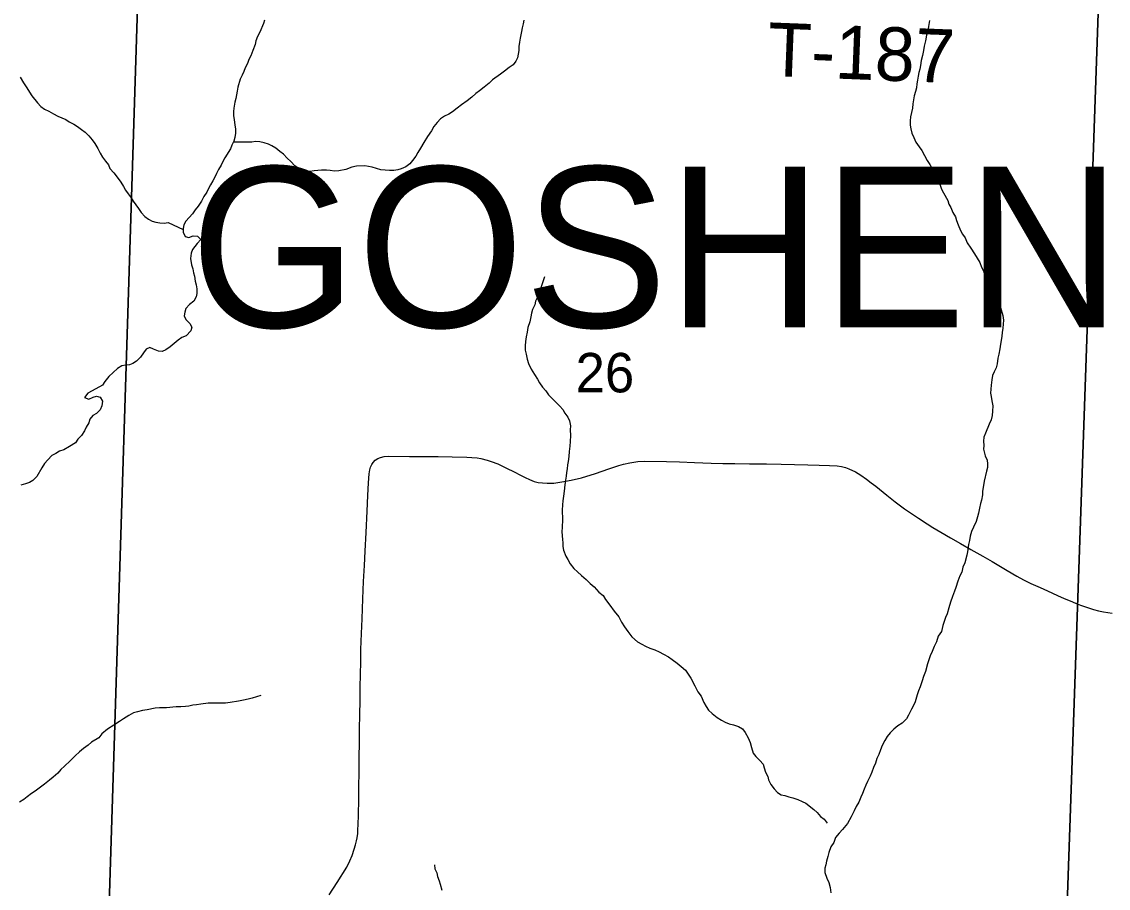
# Model space of a CAD drawing. Extents: x -7.9 to 76.1, y 0 to 22.
# Drawn here: x 6.235 to 7.388, y 19.274 to 20.193 of the extents above; entities that cross this region are included whole.
import ezdxf

# ---------------------------------------------------------------- set-up
doc = ezdxf.new("R2010")
doc.units = 0
for name, color, linetype in [('GM_X_Minor_River', 7, 'Continuous'), ('GM_X_Section', 7, 'Continuous'), ('GM_X_Section_Text', 7, 'Continuous'), ('GM_X_Township_Road', 7, 'Continuous'), ('GM_X_Township_Road_Text', 7, 'Continuous'), ('GM_X_Township_Text', 7, 'Continuous')]:
    doc.layers.add(name, color=color, linetype=linetype)

msp = doc.modelspace()

# ---------------------------------------------------------------- linework, layer by layer
at = {"layer": 'GM_X_Minor_River'}
for points in [[(6.4923, 20.1951), (6.4912, 20.1913), (6.4872, 20.1821), (6.485, 20.1775), (6.4831, 20.173), (6.4824, 20.1692), (6.4799, 20.1627), (6.4777, 20.1573), (6.4758, 20.1531), (6.4744, 20.1489), (6.4718, 20.1443), (6.4703, 20.1405), (6.4685, 20.1367), (6.4666, 20.1325), (6.4641, 20.1238), (6.4634, 20.1196), (6.462, 20.112), (6.4609, 20.1078), (6.4598, 20.1017), (6.4595, 20.0979), (6.4596, 20.0937), (6.46, 20.0892), (6.4608, 20.0839), (6.4616, 20.0793), (6.4617, 20.0752), (6.461, 20.0706), (6.4599, 20.0664), (6.4577, 20.0622), (6.4562, 20.0584), (6.4503, 20.0488), (6.4481, 20.045), (6.4462, 20.0412), (6.4436, 20.0366), (6.4414, 20.0324), (6.4396, 20.0282), (6.4374, 20.0244), (6.4351, 20.0202), (6.4329, 20.0163), (6.4311, 20.0125), (6.4281, 20.0079), (6.4255, 20.0029), (6.4218, 19.9976), (6.4188, 19.9937), (6.4158, 19.9895), (6.4087, 19.9815), (6.4069, 19.9776), (6.4062, 19.9738), (6.4062, 19.9701), (6.4082, 19.9655), (6.412, 19.9644), (6.4165, 19.966), (6.4211, 19.9657), (6.4249, 19.9623), (6.4208, 19.9581), (6.416, 19.9516), (6.4145, 19.9478), (6.4138, 19.9421), (6.415, 19.9353), (6.4162, 19.9311), (6.417, 19.9269), (6.4179, 19.9232), (6.4187, 19.9179), (6.4199, 19.9141), (6.4207, 19.9099), (6.4204, 19.905), (6.4197, 19.9012), (6.4175, 19.8966), (6.4126, 19.8931), (6.4088, 19.8889), (6.4077, 19.8851), (6.407, 19.8813), (6.409, 19.8771), (6.4132, 19.873), (6.4152, 19.8692), (6.4141, 19.8651), (6.4092, 19.8601), (6.4047, 19.8581), (6.4006, 19.8554), (6.3923, 19.8484), (6.3878, 19.845), (6.3837, 19.8434), (6.3799, 19.8437), (6.3745, 19.8459), (6.3707, 19.8474), (6.3666, 19.8458), (6.364, 19.842), (6.3606, 19.8374), (6.3565, 19.8332), (6.3527, 19.8304), (6.349, 19.8293), (6.3448, 19.8288), (6.341, 19.828)], [(6.7676, 20.195), (6.7669, 20.1912), (6.7658, 20.1867), (6.7651, 20.1829), (6.7637, 20.176), (6.763, 20.1718), (6.7623, 20.1669), (6.762, 20.1627), (6.7616, 20.1589), (6.7606, 20.1551), (6.7591, 20.1513), (6.7561, 20.1475), (6.752, 20.1448), (6.7471, 20.1409), (6.7426, 20.1378), (6.7343, 20.1316), (6.7306, 20.1281), (6.7253, 20.1239), (6.7205, 20.12), (6.7167, 20.117), (6.7122, 20.1131), (6.7073, 20.1092), (6.7013, 20.105), (6.6968, 20.1015), (6.6916, 20.0976), (6.6878, 20.0953), (6.6833, 20.093), (6.6791, 20.0903), (6.6754, 20.0864), (6.6721, 20.0822), (6.6695, 20.0776), (6.6654, 20.0715), (6.6613, 20.065), (6.6579, 20.0592), (6.655, 20.0546), (6.6528, 20.0508), (6.6494, 20.0462), (6.6464, 20.0424), (6.6423, 20.0393), (6.6374, 20.0373), (6.6336, 20.0361), (6.6295, 20.0353), (6.6249, 20.0353), (6.6203, 20.0356), (6.6158, 20.0363), (6.6112, 20.0374), (6.6067, 20.0388), (6.6025, 20.0395), (6.5987, 20.0402), (6.59, 20.0401), (6.585, 20.0389), (6.5786, 20.0365), (6.5711, 20.0349), (6.5665, 20.0348), (6.562, 20.0355), (6.5582, 20.0359), (6.5529, 20.0358), (6.5449, 20.0349), (6.5404, 20.0345), (6.5366, 20.0348), (6.5328, 20.0355), (6.5286, 20.0374), (6.5244, 20.0403), (6.5201, 20.0448), (6.5163, 20.0486), (6.5124, 20.0527), (6.5086, 20.0557), (6.5044, 20.059), (6.5002, 20.0616), (6.4964, 20.0635), (6.4918, 20.0649), (6.4872, 20.066), (6.4827, 20.0663), (6.4789, 20.0655), (6.4594, 20.0654)], [(7.198, 20.1945), (7.1969, 20.1884), (7.1959, 20.1838), (7.1948, 20.1789), (7.1937, 20.1732), (7.1923, 20.1675), (7.1916, 20.1629), (7.1905, 20.1576), (7.1891, 20.1522), (7.1884, 20.1469), (7.1877, 20.1431), (7.1866, 20.1393), (7.1859, 20.1355), (7.1852, 20.1313), (7.1845, 20.1275), (7.1842, 20.123), (7.1831, 20.1191), (7.1816, 20.1146), (7.1802, 20.1062), (7.1799, 20.1016), (7.1777, 20.0925), (7.1774, 20.088), (7.1775, 20.0834), (7.1779, 20.0796), (7.1791, 20.0751), (7.1811, 20.0705), (7.1834, 20.0656), (7.1869, 20.0604), (7.1896, 20.0566), (7.1954, 20.0461), (7.1981, 20.0419), (7.2028, 20.0329), (7.2051, 20.0288), (7.2091, 20.0197), (7.2106, 20.0156), (7.2126, 20.0118), (7.2172, 20.0035), (7.2184, 19.9997), (7.2204, 19.996), (7.2227, 19.9907), (7.2254, 19.9862), (7.2266, 19.9824), (7.2282, 19.9779), (7.2309, 19.9718), (7.2329, 19.968), (7.2356, 19.9639), (7.2379, 19.9586), (7.2418, 19.953), (7.2457, 19.947), (7.2484, 19.9425), (7.2511, 19.9376), (7.2531, 19.9327), (7.255, 19.9289), (7.2578, 19.9191), (7.259, 19.9145), (7.2598, 19.91), (7.2614, 19.9058), (7.2649, 19.9013), (7.2687, 19.898), (7.2714, 19.8942), (7.273, 19.8901), (7.2757, 19.8814), (7.2762, 19.8764), (7.2755, 19.8681), (7.2749, 19.8635), (7.2745, 19.8597), (7.2738, 19.8548), (7.2731, 19.851), (7.2724, 19.846), (7.2714, 19.8403), (7.2703, 19.8361), (7.2696, 19.8301), (7.2685, 19.8259), (7.2663, 19.8217), (7.2648, 19.8178), (7.2638, 19.8133), (7.2631, 19.8076), (7.2624, 19.7992), (7.2633, 19.7954), (7.2641, 19.7909), (7.2649, 19.7856), (7.2646, 19.7799), (7.2643, 19.7753), (7.2632, 19.7708)], [(6.233, 20.1346), (6.2365, 20.1286), (6.24, 20.123), (6.2431, 20.1185), (6.2454, 20.1147), (6.2516, 20.1072), (6.255, 20.1035), (6.2589, 20.1005), (6.2635, 20.0983), (6.2684, 20.0957), (6.273, 20.0931), (6.2814, 20.0894), (6.2852, 20.0872), (6.2902, 20.0846), (6.294, 20.082), (6.2982, 20.079), (6.302, 20.076), (6.3059, 20.0723), (6.3094, 20.0681), (6.3124, 20.064), (6.3156, 20.0587), (6.3179, 20.0538), (6.3206, 20.0497), (6.3237, 20.0452), (6.3268, 20.0414), (6.3283, 20.0377), (6.3326, 20.0328), (6.3361, 20.0283), (6.3399, 20.023), (6.3426, 20.0185), (6.345, 20.0147), (6.3477, 20.0106), (6.3508, 20.0065), (6.3531, 20.0027), (6.3585, 19.9952), (6.3616, 19.9907), (6.3654, 19.9866), (6.3693, 19.9836), (6.3731, 19.9817), (6.3769, 19.9807), (6.3814, 19.98), (6.386, 19.9796), (6.3902, 19.9801), (6.4062, 19.9727)], [(6.7895, 19.9225), (6.7865, 19.9141), (6.7847, 19.9092), (6.7829, 19.9046), (6.7818, 19.9008), (6.78, 19.8966), (6.7792, 19.8928), (6.7767, 19.8878), (6.7756, 19.884), (6.7749, 19.8802), (6.7738, 19.8749), (6.7716, 19.8688), (6.7709, 19.8638), (6.7698, 19.8589), (6.7691, 19.854), (6.7688, 19.8494), (6.7689, 19.8448), (6.7701, 19.8403), (6.7709, 19.835), (6.7725, 19.8305), (6.7752, 19.8244), (6.7787, 19.8188), (6.7818, 19.8139), (6.7841, 19.8101), (6.7872, 19.8056), (6.7907, 19.8015), (6.7938, 19.7974), (6.7973, 19.7936), (6.8015, 19.7895), (6.8057, 19.7854), (6.8088, 19.7816), (6.8111, 19.7779), (6.8142, 19.7737), (6.8158, 19.7696), (6.817, 19.7643), (6.8167, 19.7601), (6.8168, 19.7541), (6.8165, 19.7476), (6.8161, 19.7427), (6.8155, 19.737), (6.8152, 19.732), (6.8145, 19.7267), (6.8138, 19.7229), (6.8134, 19.7187), (6.8127, 19.7149), (6.8124, 19.7111), (6.8117, 19.7069), (6.811, 19.7016), (6.8103, 19.6952), (6.8096, 19.6898), (6.809, 19.6849), (6.8086, 19.6807), (6.8083, 19.675), (6.8085, 19.6648), (6.8082, 19.6564), (6.8079, 19.6522), (6.8083, 19.6477), (6.8084, 19.6439), (6.8088, 19.6401), (6.8089, 19.6363), (6.8097, 19.6325), (6.812, 19.6261), (6.8143, 19.6224), (6.8167, 19.6178), (6.8205, 19.613), (6.8244, 19.6096), (6.8286, 19.6055), (6.8336, 19.6014), (6.8378, 19.5969), (6.842, 19.5935), (6.847, 19.5879), (6.8516, 19.5842), (6.854, 19.58), (6.8586, 19.574), (6.8632, 19.5676), (6.8682, 19.5616), (6.871, 19.556), (6.8741, 19.5511), (6.8779, 19.5462), (6.8822, 19.5406), (6.8879, 19.5353), (6.8925, 19.5327), (6.8967, 19.5305), (6.9013, 19.5283), (6.9066, 19.5265), (6.9112, 19.5246), (6.9158, 19.522), (6.9208, 19.5191), (6.925, 19.5165), (6.93, 19.5124), (6.9342, 19.509), (6.9388, 19.5049), (6.9419, 19.5008), (6.9446, 19.4966), (6.9489, 19.4883), (6.952, 19.4819), (6.9555, 19.4774), (6.9586, 19.4706), (6.9609, 19.4665), (6.9632, 19.4627), (6.9671, 19.459)], [(6.341, 19.828), (6.3365, 19.8253), (6.3316, 19.8211), (6.3271, 19.8168), (6.323, 19.8115), (6.3204, 19.8076), (6.3095, 19.8014), (6.305, 19.7991), (6.3013, 19.7945), (6.3059, 19.7926), (6.3104, 19.795), (6.3142, 19.7958), (6.318, 19.7947), (6.3203, 19.7905), (6.3196, 19.7856), (6.3178, 19.7814), (6.314, 19.7776), (6.3103, 19.7752), (6.3069, 19.7714), (6.3058, 19.7676), (6.3032, 19.763), (6.3014, 19.7592), (6.298, 19.7542), (6.2943, 19.7503), (6.2917, 19.7465), (6.2853, 19.7423), (6.2793, 19.7388), (6.2747, 19.7376), (6.271, 19.7352), (6.2668, 19.7329), (6.2624, 19.7283), (6.259, 19.7244), (6.256, 19.7199), (6.2508, 19.7107), (6.2467, 19.7064), (6.243, 19.7041), (6.2388, 19.7029), (6.2339, 19.7013)], [(7.2632, 19.7708), (7.261, 19.7662), (7.2573, 19.7567), (7.2555, 19.7525), (7.2552, 19.7483), (7.2556, 19.7437), (7.2553, 19.7396), (7.2569, 19.7324), (7.2589, 19.7278), (7.2593, 19.7241), (7.2593, 19.7203), (7.2582, 19.7164), (7.2557, 19.7058), (7.255, 19.7012), (7.254, 19.6951), (7.254, 19.691), (7.253, 19.6856), (7.2519, 19.6818), (7.2508, 19.6769), (7.2497, 19.6716), (7.2487, 19.6677), (7.2472, 19.6628), (7.2446, 19.6567), (7.2424, 19.6521), (7.241, 19.6472), (7.2403, 19.6426), (7.2392, 19.6384), (7.2382, 19.6308), (7.2375, 19.627), (7.2353, 19.619), (7.2331, 19.6144), (7.232, 19.6091), (7.2302, 19.6053), (7.228, 19.5995), (7.2258, 19.5927), (7.2243, 19.5889), (7.2221, 19.5831), (7.2203, 19.5771), (7.2185, 19.5713), (7.2167, 19.5649), (7.2148, 19.561), (7.2134, 19.5568), (7.2119, 19.5523), (7.2105, 19.5462), (7.2071, 19.5412), (7.2053, 19.5351), (7.2027, 19.5301), (7.2005, 19.5248), (7.1987, 19.5202), (7.1972, 19.516), (7.1958, 19.5118), (7.1936, 19.5038), (7.1914, 19.4985), (7.19, 19.4939), (7.1881, 19.4874), (7.1863, 19.4832), (7.1848, 19.479), (7.1827, 19.4714), (7.1808, 19.4676), (7.1786, 19.4638), (7.1757, 19.4573), (7.1734, 19.4535), (7.1689, 19.4489), (7.1644, 19.4458), (7.1599, 19.4423), (7.1562, 19.4384), (7.1528, 19.4346), (7.1506, 19.4304), (7.1476, 19.425), (7.1458, 19.4205), (7.144, 19.4155), (7.1418, 19.4113), (7.1407, 19.4063), (7.1385, 19.4018), (7.1367, 19.3968), (7.1348, 19.3926), (7.1322, 19.3869), (7.1304, 19.3831), (7.1286, 19.3789), (7.1267, 19.3743), (7.1249, 19.3701), (7.123, 19.3651), (7.1201, 19.3605), (7.1179, 19.3556), (7.1149, 19.3495), (7.1108, 19.3422), (7.1056, 19.336), (7.1019, 19.3322), (7.0981, 19.3276), (7.0963, 19.3223), (7.093, 19.3177), (7.0912, 19.3116), (7.0901, 19.3074), (7.0886, 19.3024), (7.0879, 19.2986), (7.0868, 19.2948), (7.0869, 19.2902), (7.0889, 19.2842), (7.0912, 19.2797), (7.0924, 19.2744), (7.0933, 19.2687)], [(6.4883, 19.4783), (6.4838, 19.4767), (6.4792, 19.4755), (6.4751, 19.4743), (6.4702, 19.4731), (6.4649, 19.4723), (6.4558, 19.4706), (6.4509, 19.4702), (6.4327, 19.4699), (6.4247, 19.4691), (6.4202, 19.4682), (6.4164, 19.4678), (6.4122, 19.467), (6.4084, 19.4666), (6.4035, 19.4661), (6.3986, 19.466), (6.3884, 19.4651), (6.3808, 19.465), (6.3762, 19.4646), (6.3679, 19.463), (6.363, 19.4621), (6.3577, 19.4609), (6.3535, 19.4597), (6.3483, 19.457), (6.3426, 19.4535), (6.3385, 19.4504), (6.3325, 19.4465), (6.3257, 19.4423), (6.3197, 19.4373), (6.3164, 19.4334), (6.3088, 19.4288), (6.3051, 19.4253), (6.3002, 19.4218), (6.2961, 19.4184), (6.2916, 19.4141), (6.286, 19.4087), (6.28, 19.4033), (6.2762, 19.3995), (6.2729, 19.3956), (6.268, 19.3914), (6.2643, 19.3883), (6.259, 19.3841), (6.2534, 19.3798), (6.2489, 19.3767), (6.2451, 19.374), (6.2406, 19.3705), (6.2369, 19.3678), (6.2323, 19.3651)], [(6.9671, 19.459), (6.9724, 19.4549), (6.977, 19.4519), (6.9812, 19.4497), (6.9854, 19.4482), (6.99, 19.4472), (6.9953, 19.4453), (6.9995, 19.4427), (7.0022, 19.439), (7.0053, 19.4333), (7.0077, 19.4281), (7.0089, 19.4231), (7.0109, 19.4171), (7.0136, 19.4133), (7.0178, 19.4092), (7.0213, 19.4051), (7.0225, 19.4013), (7.024, 19.3968), (7.0264, 19.3923), (7.0272, 19.3885), (7.0295, 19.3836), (7.033, 19.3791), (7.0365, 19.3753), (7.0403, 19.3727), (7.0445, 19.372), (7.0487, 19.3706), (7.0528, 19.3695), (7.0582, 19.3676), (7.0627, 19.3658), (7.0666, 19.364), (7.075, 19.3573), (7.0788, 19.3539), (7.0823, 19.3498), (7.0861, 19.3468), (7.0892, 19.3426)], [(6.6727, 19.2986), (6.6732, 19.2941), (6.6751, 19.2899), (6.6759, 19.2862), (6.6775, 19.2816), (6.6787, 19.2779), (6.6803, 19.2714)]]:
    msp.add_lwpolyline(points, dxfattribs=at)
at = {"layer": 'GM_X_Section'}
for points in [[(5.4689, 20.2672), (5.4695, 20.2752), (6.3589, 20.2537), (6.3267, 19.2345), (5.4474, 19.2561)], [(6.3589, 20.2537), (7.3774, 20.223), (7.3421, 19.2056), (6.3267, 19.2345)], [(7.3774, 20.223), (8.3939, 20.1994), (8.3601, 19.1779), (7.3421, 19.2056)]]:
    msp.add_lwpolyline(points, close=True, dxfattribs=at)
at = {"layer": 'GM_X_Township_Road'}
msp.add_lwpolyline([(6.561, 19.2667), (6.5695, 19.2797), (6.5795, 19.2958), (6.5829, 19.3028), (6.5852, 19.3082), (6.5876, 19.3152), (6.589, 19.3198), (6.59, 19.3238), (6.5906, 19.3271), (6.5913, 19.3316), (6.5915, 19.3354), (6.5918, 19.3412), (6.592, 19.3511), (6.5923, 19.3681), (6.5924, 19.382), (6.5926, 19.3961), (6.5928, 19.4119), (6.593, 19.4288), (6.5932, 19.4429), (6.5934, 19.4577), (6.5937, 19.4728), (6.5939, 19.4877), (6.5941, 19.4999), (6.5944, 19.5146), (6.5946, 19.5271), (6.5952, 19.5438), (6.5958, 19.5594), (6.5966, 19.5806), (6.5974, 19.599), (6.5983, 19.6163), (6.5992, 19.6315), (6.6003, 19.6513), (6.6013, 19.6739), (6.602, 19.6904), (6.6027, 19.7039), (6.6034, 19.7136), (6.6041, 19.7178), (6.6049, 19.7206), (6.6061, 19.7234), (6.6075, 19.7256), (6.6099, 19.728), (6.6126, 19.7296), (6.6155, 19.7309), (6.6193, 19.7318), (6.6242, 19.7321), (6.6461, 19.732), (6.6617, 19.7319), (6.6764, 19.7317), (6.6913, 19.7314), (6.7069, 19.7311), (6.7124, 19.7308), (6.7181, 19.7303), (6.7218, 19.7297), (6.7286, 19.7281), (6.7329, 19.7265), (6.7397, 19.724), (6.7498, 19.7192), (6.7566, 19.7158), (6.7646, 19.7116), (6.7687, 19.7095), (6.7733, 19.7074), (6.7784, 19.7054), (6.7826, 19.7044), (6.7874, 19.7038), (6.7921, 19.7035), (6.7993, 19.7037), (6.8079, 19.705), (6.8178, 19.7067), (6.8285, 19.7092), (6.8434, 19.7139), (6.8578, 19.7188), (6.8683, 19.7224), (6.8731, 19.7238), (6.88, 19.7253), (6.8884, 19.7264), (6.8957, 19.7268), (6.9187, 19.7266), (6.9325, 19.7261), (6.9485, 19.7254), (6.9663, 19.7247), (6.9785, 19.7244), (6.9913, 19.7243), (7.0068, 19.7241), (7.025, 19.7239), (7.0405, 19.7236), (7.0547, 19.7233), (7.0688, 19.7229), (7.0808, 19.7226), (7.0917, 19.7224), (7.0998, 19.7219), (7.1044, 19.7213), (7.1086, 19.7202), (7.1124, 19.7187), (7.1192, 19.7154), (7.1249, 19.7121), (7.1309, 19.7078), (7.1361, 19.7039), (7.1408, 19.7003), (7.1524, 19.6907), (7.1614, 19.6839), (7.1713, 19.6764), (7.1799, 19.6705), (7.1861, 19.6664), (7.1955, 19.6603), (7.2013, 19.6566), (7.2099, 19.6515), (7.2201, 19.6454), (7.2307, 19.6394), (7.2417, 19.6332), (7.2543, 19.6261), (7.2644, 19.6203), (7.2802, 19.6109), (7.2905, 19.6048), (7.2975, 19.601), (7.3055, 19.5972), (7.3153, 19.5928), (7.3232, 19.5893), (7.3337, 19.5843), (7.3408, 19.5812), (7.3471, 19.5785), (7.3527, 19.5761), (7.3581, 19.574), (7.3653, 19.5715), (7.3719, 19.5695), (7.3771, 19.5681), (7.3826, 19.567), (7.3915, 19.5656)], dxfattribs=at)

# ---------------------------------------------------------------- texts
at = {"layer": 'GM_X_Section_Text'}
msp.add_text('26', height=0.04186, rotation=0, dxfattribs=at).set_placement((6.8223, 19.7999))
at = {"layer": 'GM_X_Township_Road_Text'}
msp.add_text('T-187', height=0.05682, rotation=357.7544, dxfattribs=at).set_placement((7.0251, 20.1359))
at = {"layer": 'GM_X_Township_Text'}
msp.add_text('GOSHEN', height=0.17045, rotation=0, dxfattribs=at).set_placement((6.4133, 19.8689))

doc.saveas('drawing.dxf')
